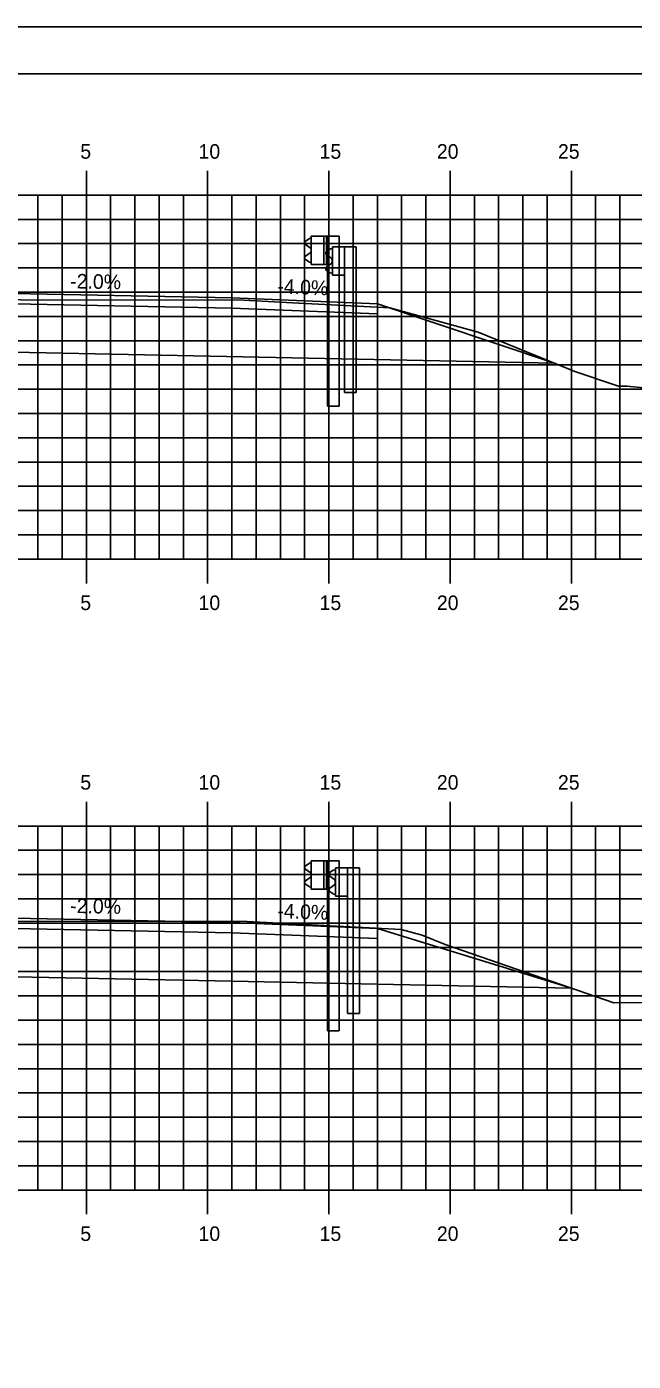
# Model space of a CAD drawing. Extents: x 2194004 to 2194525, y 863888 to 863998.
# Drawn here: x 2194257.5 to 2194282.5, y 863943.4 to 863998.4 of the extents above; entities that cross this region are included whole.
import ezdxf

# ---------------------------------------------------------------- set-up
doc = ezdxf.new("R2010")
doc.units = 0
for name, color, linetype in [('ANNOTATION', 7, 'Continuous'), ('BORDER', 7, 'Continuous'), ('D_Guardrail_Beam_Lt', 7, 'Continuous'), ('H_V ANNOTATION', 7, 'Continuous'), ('MAJOR', 7, 'Continuous'), ('MINOR', 7, 'Continuous'), ('PLOT BOUNDARY', 7, 'Continuous'), ('S_Guardrail_Beam', 7, 'Continuous'), ('S_Roadway_Centerline', 7, 'Continuous'), ('TEMPLATE', 7, 'Continuous')]:
    doc.layers.add(name, color=color, linetype=linetype)

msp = doc.modelspace()

# ---------------------------------------------------------------- linework, layer by layer
at = {"layer": 'BORDER'}
msp.add_lwpolyline([(2194179.986, 863891.446), (2194339.986, 863891.446), (2194339.986, 863996.446), (2194179.986, 863996.446)], close=True, dxfattribs=at)
at = {"layer": 'D_Guardrail_Beam_Lt'}
for p, q in [((2194269.167, 863989.648), (2194269.024, 863989.548)), ((2194269.257, 863989.669), (2194269.183, 863989.655)), ((2194269.257, 863989.752), (2194269.945, 863989.752)), ((2194269.257, 863988.586), (2194269.257, 863989.752)), ((2194269.778, 863989.752), (2194269.778, 863988.586)), ((2194269.882, 863989.752), (2194269.882, 863988.586)), ((2194269.945, 863989.752), (2194270.415, 863989.752)), ((2194269.945, 863989.752), (2194269.945, 863988.586)), ((2194270.415, 863989.752), (2194270.415, 863982.752)), ((2194269.024, 863989.405), (2194269.219, 863989.269)), ((2194269.219, 863989.07), (2194269.024, 863988.933)), ((2194269.253, 863989.204), (2194269.253, 863989.134)), ((2194269.024, 863988.79), (2194269.167, 863988.69)), ((2194269.183, 863988.684), (2194269.257, 863988.669)), ((2194269.945, 863988.586), (2194269.257, 863988.586)), ((2194269.924, 863982.752), (2194269.924, 863988.586)), ((2194269.924, 863982.752), (2194270.415, 863982.752)), ((2194269.167, 863963.908), (2194269.024, 863963.808)), ((2194269.024, 863963.665), (2194269.219, 863963.529)), ((2194269.257, 863963.929), (2194269.183, 863963.915)), ((2194269.257, 863964.012), (2194269.945, 863964.012)), ((2194269.257, 863962.846), (2194269.257, 863964.012)), ((2194269.778, 863964.012), (2194269.778, 863962.846)), ((2194269.882, 863964.012), (2194269.882, 863962.846)), ((2194269.945, 863964.012), (2194270.415, 863964.012)), ((2194269.945, 863964.012), (2194269.945, 863962.846)), ((2194270.415, 863964.012), (2194270.415, 863957.012)), ((2194269.219, 863963.33), (2194269.024, 863963.193)), ((2194269.253, 863963.464), (2194269.253, 863963.394)), ((2194269.024, 863963.05), (2194269.167, 863962.95)), ((2194269.183, 863962.944), (2194269.257, 863962.929)), ((2194269.945, 863962.846), (2194269.257, 863962.846)), ((2194269.924, 863957.012), (2194269.924, 863962.846)), ((2194269.924, 863957.012), (2194270.415, 863957.012))]:
    msp.add_line(p, q, dxfattribs=at)
for centre, major_axis, start_param, end_param in [((2194269.074, 863989.476), (-0.0877, 0), 5.323254, 7.243116), ((2194269.191, 863989.614), (-0.0417, 0), 4.907132, 5.323254), ((2194269.174, 863989.204), (0.0789, 0), 0, 0.959931), ((2194269.174, 863989.134), (0.0789, 0), 5.323254, 6.283185), ((2194269.074, 863988.862), (-0.0877, 0), 5.323254, 7.243116), ((2194269.191, 863988.724), (-0.0417, 0), 0.959931, 1.376053), ((2194269.074, 863963.736), (-0.0877, 0), 5.323254, 7.243116), ((2194269.191, 863963.874), (-0.0417, 0), 4.907132, 5.323254), ((2194269.074, 863963.122), (-0.0877, 0), 5.323254, 7.243116), ((2194269.174, 863963.464), (0.0789, 0), 0, 0.959931), ((2194269.174, 863963.394), (0.0789, 0), 5.323254, 6.283185), ((2194269.191, 863962.984), (-0.0417, 0), 0.959931, 1.376053)]:
    msp.add_ellipse(centre, major_axis=major_axis, ratio=0.995501, start_param=start_param, end_param=end_param, dxfattribs=at)
at = {"layer": 'MAJOR'}
for p, q in [((2194259.986, 863992.448), (2194259.986, 863991.446)), ((2194264.986, 863992.448), (2194264.986, 863991.446)), ((2194269.986, 863992.448), (2194269.986, 863991.446)), ((2194274.986, 863992.448), (2194274.986, 863991.446)), ((2194279.986, 863992.448), (2194279.986, 863991.446)), ((2194184.986, 863991.446), (2194324.986, 863991.446)), ((2194259.986, 863976.446), (2194259.986, 863991.446)), ((2194264.986, 863976.446), (2194264.986, 863991.446)), ((2194269.986, 863976.446), (2194269.986, 863991.446)), ((2194274.986, 863976.446), (2194274.986, 863991.446)), ((2194279.986, 863976.446), (2194279.986, 863991.446)), ((2194184.986, 863986.446), (2194324.986, 863986.446)), ((2194184.986, 863981.446), (2194324.986, 863981.446)), ((2194184.986, 863976.446), (2194324.986, 863976.446)), ((2194259.986, 863975.444), (2194259.986, 863976.446)), ((2194264.986, 863975.444), (2194264.986, 863976.446)), ((2194269.986, 863975.444), (2194269.986, 863976.446)), ((2194274.986, 863975.444), (2194274.986, 863976.446)), ((2194279.986, 863975.444), (2194279.986, 863976.446)), ((2194259.986, 863966.448), (2194259.986, 863965.446)), ((2194264.986, 863966.448), (2194264.986, 863965.446)), ((2194269.986, 863966.448), (2194269.986, 863965.446)), ((2194274.986, 863966.448), (2194274.986, 863965.446)), ((2194279.986, 863966.448), (2194279.986, 863965.446)), ((2194184.986, 863965.446), (2194324.986, 863965.446)), ((2194259.986, 863950.446), (2194259.986, 863965.446)), ((2194264.986, 863950.446), (2194264.986, 863965.446)), ((2194269.986, 863950.446), (2194269.986, 863965.446)), ((2194274.986, 863950.446), (2194274.986, 863965.446)), ((2194279.986, 863950.446), (2194279.986, 863965.446)), ((2194184.986, 863960.446), (2194324.986, 863960.446)), ((2194184.986, 863955.446), (2194324.986, 863955.446)), ((2194184.986, 863950.446), (2194324.986, 863950.446)), ((2194259.986, 863949.444), (2194259.986, 863950.446)), ((2194264.986, 863949.444), (2194264.986, 863950.446)), ((2194269.986, 863949.444), (2194269.986, 863950.446)), ((2194274.986, 863949.444), (2194274.986, 863950.446)), ((2194279.986, 863949.444), (2194279.986, 863950.446))]:
    msp.add_line(p, q, dxfattribs=at)
at = {"layer": 'MINOR'}
for p, q in [((2194257.986, 863976.446), (2194257.986, 863991.446)), ((2194258.986, 863976.446), (2194258.986, 863991.446)), ((2194260.986, 863976.446), (2194260.986, 863991.446)), ((2194261.986, 863976.446), (2194261.986, 863991.446)), ((2194262.986, 863976.446), (2194262.986, 863991.446)), ((2194263.986, 863976.446), (2194263.986, 863991.446)), ((2194265.986, 863976.446), (2194265.986, 863991.446)), ((2194266.986, 863976.446), (2194266.986, 863991.446)), ((2194267.986, 863976.446), (2194267.986, 863991.446)), ((2194268.986, 863976.446), (2194268.986, 863991.446)), ((2194270.986, 863976.446), (2194270.986, 863991.446)), ((2194271.986, 863976.446), (2194271.986, 863991.446)), ((2194272.986, 863976.446), (2194272.986, 863991.446)), ((2194273.986, 863976.446), (2194273.986, 863991.446)), ((2194275.986, 863976.446), (2194275.986, 863991.446)), ((2194276.986, 863976.446), (2194276.986, 863991.446)), ((2194277.986, 863976.446), (2194277.986, 863991.446)), ((2194278.986, 863976.446), (2194278.986, 863991.446)), ((2194280.986, 863976.446), (2194280.986, 863991.446)), ((2194281.986, 863976.446), (2194281.986, 863991.446)), ((2194184.986, 863990.446), (2194324.986, 863990.446)), ((2194184.986, 863989.446), (2194324.986, 863989.446)), ((2194184.986, 863988.446), (2194324.986, 863988.446)), ((2194184.986, 863987.446), (2194324.986, 863987.446)), ((2194184.986, 863985.446), (2194324.986, 863985.446)), ((2194184.986, 863984.446), (2194324.986, 863984.446)), ((2194184.986, 863983.446), (2194324.986, 863983.446)), ((2194184.986, 863982.446), (2194324.986, 863982.446)), ((2194184.986, 863980.446), (2194324.986, 863980.446)), ((2194184.986, 863979.446), (2194324.986, 863979.446)), ((2194184.986, 863978.446), (2194324.986, 863978.446)), ((2194184.986, 863977.446), (2194324.986, 863977.446)), ((2194257.986, 863950.446), (2194257.986, 863965.446)), ((2194258.986, 863950.446), (2194258.986, 863965.446)), ((2194260.986, 863950.446), (2194260.986, 863965.446)), ((2194261.986, 863950.446), (2194261.986, 863965.446)), ((2194262.986, 863950.446), (2194262.986, 863965.446)), ((2194263.986, 863950.446), (2194263.986, 863965.446)), ((2194265.986, 863950.446), (2194265.986, 863965.446)), ((2194266.986, 863950.446), (2194266.986, 863965.446)), ((2194267.986, 863950.446), (2194267.986, 863965.446)), ((2194268.986, 863950.446), (2194268.986, 863965.446)), ((2194270.986, 863950.446), (2194270.986, 863965.446)), ((2194271.986, 863950.446), (2194271.986, 863965.446)), ((2194272.986, 863950.446), (2194272.986, 863965.446)), ((2194273.986, 863950.446), (2194273.986, 863965.446)), ((2194275.986, 863950.446), (2194275.986, 863965.446)), ((2194276.986, 863950.446), (2194276.986, 863965.446)), ((2194277.986, 863950.446), (2194277.986, 863965.446)), ((2194278.986, 863950.446), (2194278.986, 863965.446)), ((2194280.986, 863950.446), (2194280.986, 863965.446)), ((2194281.986, 863950.446), (2194281.986, 863965.446)), ((2194184.986, 863964.446), (2194324.986, 863964.446)), ((2194184.986, 863963.446), (2194324.986, 863963.446)), ((2194184.986, 863962.446), (2194324.986, 863962.446)), ((2194184.986, 863961.446), (2194324.986, 863961.446)), ((2194184.986, 863959.446), (2194324.986, 863959.446)), ((2194184.986, 863958.446), (2194324.986, 863958.446)), ((2194184.986, 863957.446), (2194324.986, 863957.446)), ((2194184.986, 863956.446), (2194324.986, 863956.446)), ((2194184.986, 863954.446), (2194324.986, 863954.446)), ((2194184.986, 863953.446), (2194324.986, 863953.446)), ((2194184.986, 863952.446), (2194324.986, 863952.446)), ((2194184.986, 863951.446), (2194324.986, 863951.446))]:
    msp.add_line(p, q, dxfattribs=at)
at = {"layer": 'PLOT BOUNDARY'}
msp.add_lwpolyline([(2194171.893, 863888.387), (2194341.893, 863888.387), (2194341.893, 863998.387), (2194171.893, 863998.387)], close=True, dxfattribs=at)
at = {"layer": 'S_Guardrail_Beam'}
for p, q in [((2194270.038, 863989.224), (2194269.895, 863989.124)), ((2194269.895, 863988.981), (2194270.09, 863988.845)), ((2194270.137, 863989.246), (2194270.055, 863989.231)), ((2194270.137, 863989.318), (2194270.627, 863989.318)), ((2194270.137, 863988.152), (2194270.137, 863989.318)), ((2194270.627, 863989.318), (2194271.118, 863989.318)), ((2194270.627, 863989.318), (2194270.627, 863988.152)), ((2194271.118, 863989.318), (2194271.118, 863983.318)), ((2194270.09, 863988.625), (2194269.895, 863988.489)), ((2194270.124, 863988.781), (2194270.124, 863988.69)), ((2194269.895, 863988.346), (2194270.038, 863988.246)), ((2194270.055, 863988.239), (2194270.137, 863988.225)), ((2194270.627, 863988.152), (2194270.137, 863988.152)), ((2194270.627, 863983.318), (2194270.627, 863988.152)), ((2194270.627, 863983.318), (2194271.118, 863983.318)), ((2194270.264, 863963.719), (2194270.753, 863963.719)), ((2194270.264, 863962.552), (2194270.264, 863963.719)), ((2194270.753, 863963.719), (2194271.245, 863963.719)), ((2194270.753, 863963.719), (2194270.753, 863962.552)), ((2194271.245, 863963.719), (2194271.245, 863957.719)), ((2194270.165, 863963.624), (2194270.022, 863963.524)), ((2194270.022, 863963.381), (2194270.217, 863963.245)), ((2194270.264, 863963.646), (2194270.182, 863963.631)), ((2194270.251, 863963.181), (2194270.251, 863963.09)), ((2194270.217, 863963.025), (2194270.022, 863962.889)), ((2194270.022, 863962.746), (2194270.165, 863962.646)), ((2194270.182, 863962.639), (2194270.264, 863962.625)), ((2194270.753, 863962.552), (2194270.264, 863962.552)), ((2194270.753, 863957.719), (2194270.753, 863962.552)), ((2194270.753, 863957.719), (2194271.245, 863957.719))]:
    msp.add_line(p, q, dxfattribs=at)
for centre, major_axis, start_param, end_param in [((2194269.945, 863989.053), (-0.0877, 0), 5.323254, 7.243116), ((2194270.062, 863989.19), (-0.0417, 0), 4.886922, 5.323254), ((2194269.945, 863988.417), (-0.0877, 0), 5.323254, 7.243116), ((2194270.045, 863988.781), (0.0789, 0), 0, 0.959931), ((2194270.045, 863988.69), (0.0789, 0), 5.323254, 6.283185), ((2194270.062, 863988.28), (-0.0417, 0), 0.959931, 1.396263), ((2194270.072, 863963.453), (-0.0877, 0), 5.323254, 7.243116), ((2194270.189, 863963.59), (-0.0417, 0), 4.886922, 5.323254), ((2194270.172, 863963.181), (0.0789, 0), 0, 0.959931), ((2194270.072, 863962.818), (-0.0877, 0), 5.323254, 7.243116), ((2194270.189, 863962.68), (-0.0417, 0), 0.959931, 1.396263), ((2194270.172, 863963.09), (0.0789, 0), 5.323254, 6.283185)]:
    msp.add_ellipse(centre, major_axis=major_axis, ratio=0.995501, start_param=start_param, end_param=end_param, dxfattribs=at)
at = {"layer": 'S_Roadway_Centerline'}
for points in [[(2194213.418, 863980.464), (2194214.429, 863980.92), (2194223.452, 863983.465), (2194229.766, 863986.085), (2194237.17, 863986.524), (2194241.493, 863986.815), (2194242.245, 863986.842), (2194243.54, 863987.01), (2194250.337, 863987.069), (2194254.913, 863987.141), (2194259.636, 863987.117), (2194266.23, 863987.133), (2194268.49, 863987.008), (2194272.502, 863986.802), (2194276.144, 863985.803), (2194280.132, 863984.18), (2194281.922, 863983.566), (2194282.269, 863983.567), (2194286.889, 863983.115)], [(2194184.986, 863954.358), (2194200.571, 863955.358), (2194201.834, 863955.126), (2194206.87, 863954.31), (2194208.212, 863954.697), (2194211.397, 863954.921), (2194213.079, 863954.925), (2194215.549, 863955.904), (2194228.253, 863960.358), (2194233.476, 863960.836), (2194239.439, 863961.237), (2194243.192, 863961.374), (2194243.421, 863961.404), (2194254.114, 863961.496), (2194254.957, 863961.51), (2194255.828, 863961.505), (2194266.219, 863961.53), (2194266.624, 863961.508), (2194272.966, 863961.182), (2194273.834, 863960.944), (2194274.785, 863960.557), (2194281.743, 863958.166), (2194283.095, 863958.173)]]:
    msp.add_lwpolyline(points, dxfattribs=at)
at = {"layer": 'TEMPLATE'}
for p, q in [((2194265.986, 863987.206), (2194254.986, 863987.426)), ((2194265.986, 863986.789), (2194254.986, 863987.009)), ((2194271.986, 863986.966), (2194265.986, 863987.206)), ((2194279.291, 863984.523), (2194271.986, 863986.966)), ((2194279.291, 863984.523), (2194254.986, 863985.009)), ((2194265.986, 863961.466), (2194254.986, 863961.686)), ((2194271.986, 863961.226), (2194265.986, 863961.466)), ((2194265.986, 863961.049), (2194254.986, 863961.269)), ((2194271.986, 863961.226), (2194279.987, 863958.769))]:
    msp.add_line(p, q, dxfattribs=at)
for points in [[(2194271.986, 863986.966), (2194271.986, 863986.549), (2194265.986, 863986.789)], [(2194271.986, 863960.809), (2194271.986, 863961.226), (2194271.986, 863960.809), (2194265.986, 863961.049)], [(2194223.342, 863958.636), (2194243.986, 863959.049), (2194254.986, 863959.269), (2194265.986, 863959.049), (2194279.987, 863958.769)]]:
    msp.add_lwpolyline(points, dxfattribs=at)

# ---------------------------------------------------------------- texts
at = {"layer": 'ANNOTATION'}
for s, rotation, p in [('-2.0%', 358.8542, (2194259.315, 863987.606)), ('-4.0%', 357.7094, (2194267.853, 863987.398)), ('-2.0%', 358.8542, (2194259.315, 863961.866)), ('-4.0%', 357.7094, (2194267.853, 863961.658))]:
    msp.add_text(s, height=0.6, rotation=rotation, dxfattribs=at).set_placement(p)
at = {"layer": 'H_V ANNOTATION'}
for s, p in [('5', (2194259.737, 863992.946)), ('10', (2194264.612, 863992.946)), ('15', (2194269.604, 863992.946)), ('20', (2194274.44, 863992.946)), ('25', (2194279.432, 863992.946)), ('5', (2194259.737, 863974.346)), ('10', (2194264.612, 863974.346)), ('15', (2194269.604, 863974.346)), ('20', (2194274.44, 863974.346)), ('25', (2194279.432, 863974.346)), ('5', (2194259.737, 863966.946)), ('10', (2194264.612, 863966.946)), ('15', (2194269.604, 863966.946)), ('20', (2194274.44, 863966.946)), ('25', (2194279.432, 863966.946)), ('5', (2194259.737, 863948.346)), ('10', (2194264.612, 863948.346)), ('15', (2194269.604, 863948.346)), ('20', (2194274.44, 863948.346)), ('25', (2194279.432, 863948.346))]:
    msp.add_text(s, height=0.6, dxfattribs=at).set_placement(p)

doc.saveas('drawing.dxf')
